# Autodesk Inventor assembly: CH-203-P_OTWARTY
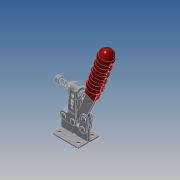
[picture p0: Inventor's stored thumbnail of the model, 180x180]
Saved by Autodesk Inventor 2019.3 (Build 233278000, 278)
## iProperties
Company: Î¢ÈíÖÐ¹ú
Created: 2015-08
Part Number: CH-203-P_OTWARTY
Material: Ogólny
Description: STEP AP203
Document SubType Name: Assembly
Designer: CADENGINEERING4
Sending System: SolidWorks 2012
Preprocessor: SwSTEP 2.0
Title: CH-203-P.STEP
Author: Î¢ÈíÓÃ»§
Revision Number: ÈÎºÎ
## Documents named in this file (9)
- E:\STRONA\Horizontal toggle clamp\CH-203-P\CH-203-P_OTWARTY.iam
- E:\STRONA\Horizontal toggle clamp\CH-203-P\203-P-01.ipt
- E:\STRONA\Horizontal toggle clamp\CH-203-P\203-P-02.ipt
- E:\STRONA\Horizontal toggle clamp\CH-203-P\225-D-06.ipt
- E:\STRONA\Horizontal toggle clamp\CH-203-P\FW516.ipt
- E:\STRONA\Horizontal toggle clamp\CH-203-P\56212-02.ipt
- E:\STRONA\Horizontal toggle clamp\CH-203-P\085012.ipt
- E:\STRONA\Horizontal toggle clamp\CH-203-P\02.iam
- E:\STRONA\Horizontal toggle clamp\CH-203-P\203-F-04.ipt
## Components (14 placed, 14 different names)
1. 203-P-01_1 — Zestawiające:10, Zestawiające:11, Zestawiające:12, Zestawiające:13, Zestawiające:14, Zestawiające:21, Zestawiające:26, Przejściowe:1
2. 203-P-02_2 — Równoległe:1, Zestawiające:5, Zestawiające:6, Zestawiające:9, Zestawiające:23, Zestawiające:24, Zestawiające:25, Zestawiające:26, Zestawiające:27
3. 225-D-06_3 — Zestawiające:21, Zestawiające:27
4. FW516_4 — Równoległe:1, Równoległe:2, Zestawiające:3, Zestawiające:6, Zestawiające:7
5. FW516_5 — Równoległe:2, Zestawiające:4, Zestawiające:5, Zestawiające:8
6. 56212-02_6 — Równoległe:3, Zestawiające:1, Zestawiające:7
7. 56212-02_7 — Zestawiające:2, Zestawiające:8
8. 085012_8 — Równoległe:3, Zestawiające:1, Zestawiające:2, Zestawiające:3, Zestawiające:4, Zestawiające:9
9. 02_9 [sub-assembly] — Zestawiające:19, Zestawiające:20, Zestawiające:22, Zestawiające:24, Przejściowe:1
10. 203-F-04_10 — Zestawiające:11, Zestawiające:13, Zestawiające:16
11. 203-F-04_11 — Zestawiające:10, Zestawiające:12, Zestawiające:15, Zestawiające:16, Zestawiające:17, Zestawiające:18, Zestawiające:19
12. 225-D-06_12 — Zestawiające:22, Zestawiające:23, Zestawiające:25
13. 225-D-06_13 — Zestawiające:17, Zestawiające:18, Zestawiające:20
14. 225-D-06_14 — Zestawiające:14, Zestawiające:15
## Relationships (31: Mate 27, Flush 3, Transitional 1)
- Równoległe:1 [Flush]: 203-P-02_2 ↔ FW516_4
- Równoległe:2 [Flush]: FW516_4 ↔ FW516_5
- Równoległe:3 [Flush]: 56212-02_6 ↔ 085012_8
- Zestawiające:1 [Mate]: 56212-02_6 ↔ 085012_8
- Zestawiające:2 [Mate]: 56212-02_7 ↔ 085012_8
- Zestawiające:3 [Mate]: FW516_4 ↔ 085012_8
- Zestawiające:4 [Mate]: FW516_5 ↔ 085012_8
- Zestawiające:5 [Mate]: 203-P-02_2 ↔ FW516_5
- Zestawiające:6 [Mate]: 203-P-02_2 ↔ FW516_4
- Zestawiające:7 [Mate]: FW516_4 ↔ 56212-02_6
- Zestawiające:8 [Mate]: FW516_5 ↔ 56212-02_7
- Zestawiające:9 [Mate]: 203-P-02_2 ↔ 085012_8
- Zestawiające:10 [Mate]: 203-P-01_1 ↔ 203-F-04_11
- Zestawiające:11 [Mate]: 203-P-01_1 ↔ 203-F-04_10
- Zestawiające:12 [Mate]: 203-P-01_1 ↔ 203-F-04_11
- Zestawiające:13 [Mate]: 203-P-01_1 ↔ 203-F-04_10
- Zestawiające:14 [Mate]: 203-P-01_1 ↔ 225-D-06_14
- Zestawiające:15 [Mate]: 203-F-04_11 ↔ 225-D-06_14
- Zestawiające:16 [Mate]: 203-F-04_10 ↔ 203-F-04_11
- Zestawiające:17 [Mate]: 203-F-04_11 ↔ 225-D-06_13
- Zestawiające:18 [Mate]: 203-F-04_11 ↔ 225-D-06_13
- Zestawiające:19 [Mate]: 02_9 ↔ 203-F-04_11
- Zestawiające:20 [Mate]: 02_9 ↔ 225-D-06_13
- Zestawiające:21 [Mate]: 203-P-01_1 ↔ 225-D-06_3
- Zestawiające:22 [Mate]: 02_9 ↔ 225-D-06_12
- Zestawiające:23 [Mate]: 203-P-02_2 ↔ 225-D-06_12
- Zestawiające:24 [Mate]: 203-P-02_2 ↔ 02_9
- Zestawiające:25 [Mate]: 203-P-02_2 ↔ 225-D-06_12
- Zestawiające:26 [Mate]: 203-P-01_1 ↔ 203-P-02_2
- Zestawiające:27 [Mate]: 203-P-02_2 ↔ 225-D-06_3
- Przejściowe:1 [Transitional]: 203-P-01_1 ↔ 02_9
